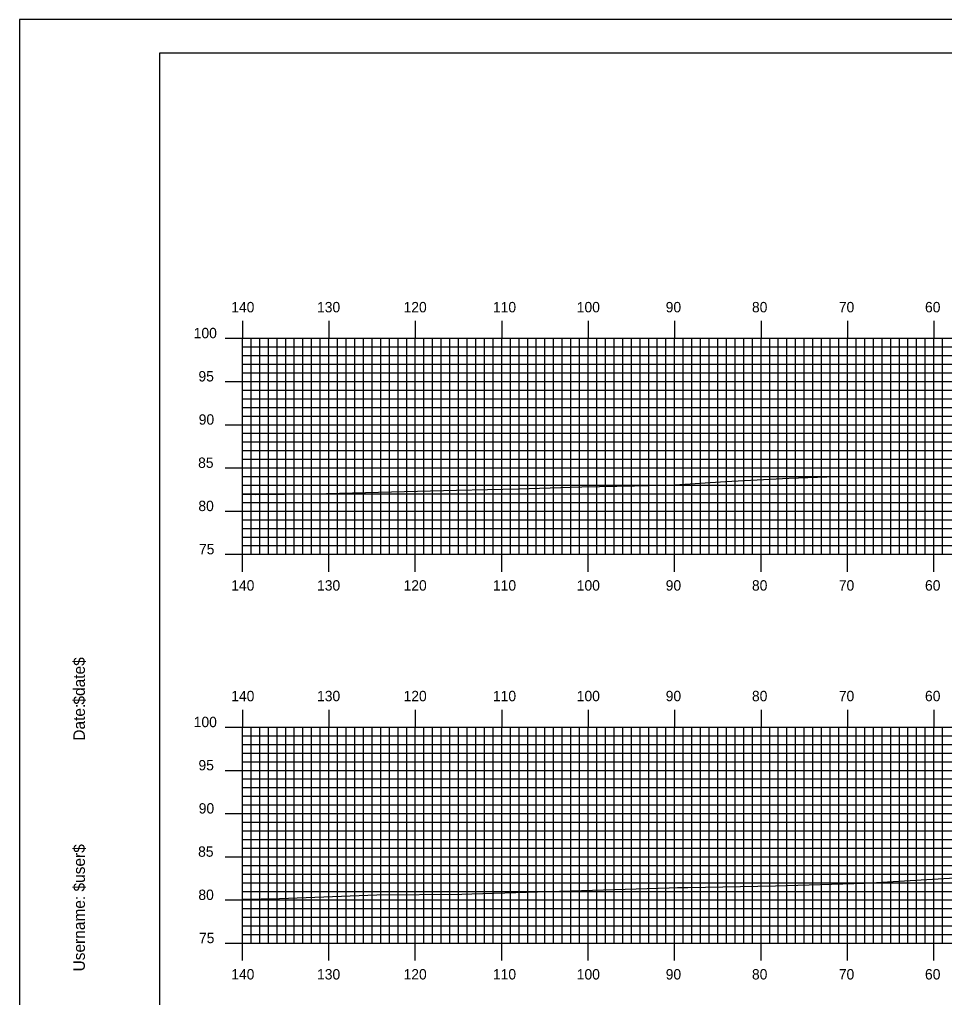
# Model space of a CAD drawing. Extents: x 1777531 to 1777875, y 442591 to 442811.
# Drawn here: x 1777531.5 to 1777638.5, y 442697.4 to 442810.5 of the extents above; entities that cross this region are included whole.
import ezdxf

# ---------------------------------------------------------------- set-up
doc = ezdxf.new("R2010")
doc.units = 0
for name, color, linetype in [('BORDER', 7, 'Continuous'), ('H_V ANNOTATION', 7, 'Continuous'), ('MAJOR', 7, 'Continuous'), ('MINOR', 7, 'Continuous'), ('PLOT BOUNDARY', 7, 'Continuous'), ('S_Roadway_Centerline', 7, 'Continuous')]:
    doc.layers.add(name, color=color, linetype=linetype)

msp = doc.modelspace()

# ---------------------------------------------------------------- linework, layer by layer
at = {"layer": 'BORDER'}
msp.add_lwpolyline([(1777547.68, 442596.67), (1777867.68, 442596.67), (1777867.68, 442806.67), (1777547.68, 442806.67)], close=True, dxfattribs=at)
at = {"layer": 'MAJOR'}
for p, q in [((1777557.28, 442775.67), (1777557.28, 442773.67)), ((1777567.28, 442775.67), (1777567.28, 442773.67)), ((1777577.28, 442775.67), (1777577.28, 442773.67)), ((1777587.28, 442775.67), (1777587.28, 442773.67)), ((1777597.28, 442775.67), (1777597.28, 442773.67)), ((1777607.28, 442775.67), (1777607.28, 442773.67)), ((1777617.28, 442775.67), (1777617.28, 442773.67)), ((1777627.28, 442775.67), (1777627.28, 442773.67)), ((1777637.28, 442775.67), (1777637.28, 442773.67)), ((1777555.27, 442773.67), (1777557.28, 442773.67)), ((1777557.28, 442773.67), (1777837.28, 442773.67)), ((1777557.28, 442748.67), (1777557.28, 442773.67)), ((1777557.28, 442748.67), (1777557.28, 442773.67)), ((1777557.28, 442773.67), (1777837.28, 442773.67)), ((1777567.28, 442748.67), (1777567.28, 442773.67)), ((1777577.28, 442748.67), (1777577.28, 442773.67)), ((1777587.28, 442748.67), (1777587.28, 442773.67)), ((1777597.28, 442748.67), (1777597.28, 442773.67)), ((1777607.28, 442748.67), (1777607.28, 442773.67)), ((1777617.28, 442748.67), (1777617.28, 442773.67)), ((1777627.28, 442748.67), (1777627.28, 442773.67)), ((1777637.28, 442748.67), (1777637.28, 442773.67)), ((1777555.27, 442768.67), (1777557.28, 442768.67)), ((1777557.28, 442768.67), (1777837.28, 442768.67)), ((1777555.27, 442763.67), (1777557.28, 442763.67)), ((1777557.28, 442763.67), (1777837.28, 442763.67)), ((1777555.27, 442758.67), (1777557.28, 442758.67)), ((1777557.28, 442758.67), (1777837.28, 442758.67)), ((1777555.27, 442753.67), (1777557.28, 442753.67)), ((1777557.28, 442753.67), (1777837.28, 442753.67)), ((1777555.27, 442748.67), (1777557.28, 442748.67)), ((1777557.28, 442748.67), (1777837.28, 442748.67)), ((1777557.28, 442748.67), (1777837.28, 442748.67)), ((1777557.28, 442746.66), (1777557.28, 442748.67)), ((1777567.28, 442746.66), (1777567.28, 442748.67)), ((1777577.28, 442746.66), (1777577.28, 442748.67)), ((1777587.28, 442746.66), (1777587.28, 442748.67)), ((1777597.28, 442746.66), (1777597.28, 442748.67)), ((1777607.28, 442746.66), (1777607.28, 442748.67)), ((1777617.28, 442746.66), (1777617.28, 442748.67)), ((1777627.28, 442746.66), (1777627.28, 442748.67)), ((1777637.28, 442746.66), (1777637.28, 442748.67)), ((1777557.28, 442730.67), (1777557.28, 442728.67)), ((1777567.28, 442730.67), (1777567.28, 442728.67)), ((1777577.28, 442730.67), (1777577.28, 442728.67)), ((1777587.28, 442730.67), (1777587.28, 442728.67)), ((1777597.28, 442730.67), (1777597.28, 442728.67)), ((1777607.28, 442730.67), (1777607.28, 442728.67)), ((1777617.28, 442730.67), (1777617.28, 442728.67)), ((1777627.28, 442730.67), (1777627.28, 442728.67)), ((1777637.28, 442730.67), (1777637.28, 442728.67)), ((1777555.27, 442728.67), (1777557.28, 442728.67)), ((1777557.28, 442728.67), (1777837.28, 442728.67)), ((1777557.28, 442703.67), (1777557.28, 442728.67)), ((1777557.28, 442703.67), (1777557.28, 442728.67)), ((1777557.28, 442728.67), (1777837.28, 442728.67)), ((1777567.28, 442703.67), (1777567.28, 442728.67)), ((1777577.28, 442703.67), (1777577.28, 442728.67)), ((1777587.28, 442703.67), (1777587.28, 442728.67)), ((1777597.28, 442703.67), (1777597.28, 442728.67)), ((1777607.28, 442703.67), (1777607.28, 442728.67)), ((1777617.28, 442703.67), (1777617.28, 442728.67)), ((1777627.28, 442703.67), (1777627.28, 442728.67)), ((1777637.28, 442703.67), (1777637.28, 442728.67)), ((1777555.27, 442723.67), (1777557.28, 442723.67)), ((1777557.28, 442723.67), (1777837.28, 442723.67)), ((1777555.27, 442718.67), (1777557.28, 442718.67)), ((1777557.28, 442718.67), (1777837.28, 442718.67)), ((1777555.27, 442713.67), (1777557.28, 442713.67)), ((1777557.28, 442713.67), (1777837.28, 442713.67)), ((1777555.27, 442708.67), (1777557.28, 442708.67)), ((1777557.28, 442708.67), (1777837.28, 442708.67)), ((1777555.27, 442703.67), (1777557.28, 442703.67)), ((1777557.28, 442703.67), (1777837.28, 442703.67)), ((1777557.28, 442703.67), (1777837.28, 442703.67)), ((1777557.28, 442701.66), (1777557.28, 442703.67)), ((1777567.28, 442701.66), (1777567.28, 442703.67)), ((1777577.28, 442701.66), (1777577.28, 442703.67)), ((1777587.28, 442701.66), (1777587.28, 442703.67)), ((1777597.28, 442701.66), (1777597.28, 442703.67)), ((1777607.28, 442701.66), (1777607.28, 442703.67)), ((1777617.28, 442701.66), (1777617.28, 442703.67)), ((1777627.28, 442701.66), (1777627.28, 442703.67)), ((1777637.28, 442701.66), (1777637.28, 442703.67))]:
    msp.add_line(p, q, dxfattribs=at)
at = {"layer": 'MINOR'}
for p, q in [((1777557.28, 442772.67), (1777837.28, 442772.67)), ((1777557.28, 442772.67), (1777559.28, 442772.67)), ((1777558.28, 442748.67), (1777558.28, 442773.67)), ((1777559.28, 442748.67), (1777559.28, 442773.67)), ((1777560.28, 442748.67), (1777560.28, 442773.67)), ((1777561.28, 442748.67), (1777561.28, 442773.67)), ((1777562.28, 442748.67), (1777562.28, 442773.67)), ((1777563.28, 442748.67), (1777563.28, 442773.67)), ((1777564.28, 442748.67), (1777564.28, 442773.67)), ((1777565.28, 442748.67), (1777565.28, 442773.67)), ((1777566.28, 442748.67), (1777566.28, 442773.67)), ((1777568.28, 442748.67), (1777568.28, 442773.67)), ((1777569.28, 442748.67), (1777569.28, 442773.67)), ((1777570.28, 442748.67), (1777570.28, 442773.67)), ((1777571.28, 442748.67), (1777571.28, 442773.67)), ((1777572.28, 442748.67), (1777572.28, 442773.67)), ((1777573.28, 442748.67), (1777573.28, 442773.67)), ((1777574.28, 442748.67), (1777574.28, 442773.67)), ((1777575.28, 442748.67), (1777575.28, 442773.67)), ((1777576.28, 442748.67), (1777576.28, 442773.67)), ((1777578.28, 442748.67), (1777578.28, 442773.67)), ((1777579.28, 442748.67), (1777579.28, 442773.67)), ((1777580.28, 442748.67), (1777580.28, 442773.67)), ((1777581.28, 442748.67), (1777581.28, 442773.67)), ((1777582.28, 442748.67), (1777582.28, 442773.67)), ((1777583.28, 442748.67), (1777583.28, 442773.67)), ((1777584.28, 442748.67), (1777584.28, 442773.67)), ((1777585.28, 442748.67), (1777585.28, 442773.67)), ((1777586.28, 442748.67), (1777586.28, 442773.67)), ((1777588.28, 442748.67), (1777588.28, 442773.67)), ((1777589.28, 442748.67), (1777589.28, 442773.67)), ((1777590.28, 442748.67), (1777590.28, 442773.67)), ((1777591.28, 442748.67), (1777591.28, 442773.67)), ((1777592.28, 442748.67), (1777592.28, 442773.67)), ((1777593.28, 442748.67), (1777593.28, 442773.67)), ((1777594.28, 442748.67), (1777594.28, 442773.67)), ((1777595.28, 442748.67), (1777595.28, 442773.67)), ((1777596.28, 442748.67), (1777596.28, 442773.67)), ((1777598.28, 442748.67), (1777598.28, 442773.67)), ((1777599.28, 442748.67), (1777599.28, 442773.67)), ((1777600.28, 442748.67), (1777600.28, 442773.67)), ((1777601.28, 442748.67), (1777601.28, 442773.67)), ((1777602.28, 442748.67), (1777602.28, 442773.67)), ((1777603.28, 442748.67), (1777603.28, 442773.67)), ((1777604.28, 442748.67), (1777604.28, 442773.67)), ((1777605.28, 442748.67), (1777605.28, 442773.67)), ((1777606.28, 442748.67), (1777606.28, 442773.67)), ((1777608.28, 442748.67), (1777608.28, 442773.67)), ((1777609.28, 442748.67), (1777609.28, 442773.67)), ((1777610.28, 442748.67), (1777610.28, 442773.67)), ((1777611.28, 442748.67), (1777611.28, 442773.67)), ((1777612.28, 442748.67), (1777612.28, 442773.67)), ((1777613.28, 442748.67), (1777613.28, 442773.67)), ((1777614.28, 442748.67), (1777614.28, 442773.67)), ((1777615.28, 442748.67), (1777615.28, 442773.67)), ((1777616.28, 442748.67), (1777616.28, 442773.67)), ((1777618.28, 442748.67), (1777618.28, 442773.67)), ((1777619.28, 442748.67), (1777619.28, 442773.67)), ((1777620.28, 442748.67), (1777620.28, 442773.67)), ((1777621.28, 442748.67), (1777621.28, 442773.67)), ((1777622.28, 442748.67), (1777622.28, 442773.67)), ((1777623.28, 442748.67), (1777623.28, 442773.67)), ((1777624.28, 442748.67), (1777624.28, 442773.67)), ((1777625.28, 442748.67), (1777625.28, 442773.67)), ((1777626.28, 442748.67), (1777626.28, 442773.67)), ((1777628.28, 442748.67), (1777628.28, 442773.67)), ((1777629.28, 442748.67), (1777629.28, 442773.67)), ((1777630.28, 442748.67), (1777630.28, 442773.67)), ((1777631.28, 442748.67), (1777631.28, 442773.67)), ((1777632.28, 442748.67), (1777632.28, 442773.67)), ((1777633.28, 442748.67), (1777633.28, 442773.67)), ((1777634.28, 442748.67), (1777634.28, 442773.67)), ((1777635.28, 442748.67), (1777635.28, 442773.67)), ((1777636.28, 442748.67), (1777636.28, 442773.67)), ((1777638.28, 442748.67), (1777638.28, 442773.67)), ((1777557.28, 442771.67), (1777837.28, 442771.67)), ((1777557.28, 442771.67), (1777559.28, 442771.67)), ((1777557.28, 442770.67), (1777837.28, 442770.67)), ((1777557.28, 442770.67), (1777559.28, 442770.67)), ((1777557.28, 442769.67), (1777837.28, 442769.67)), ((1777557.28, 442769.67), (1777559.28, 442769.67)), ((1777557.28, 442767.67), (1777837.28, 442767.67)), ((1777557.28, 442767.67), (1777559.28, 442767.67)), ((1777557.28, 442766.67), (1777837.28, 442766.67)), ((1777557.28, 442766.67), (1777559.28, 442766.67)), ((1777557.28, 442765.67), (1777837.28, 442765.67)), ((1777557.28, 442765.67), (1777559.28, 442765.67)), ((1777557.28, 442764.67), (1777837.28, 442764.67)), ((1777557.28, 442764.67), (1777559.28, 442764.67)), ((1777557.28, 442762.67), (1777837.28, 442762.67)), ((1777557.28, 442762.67), (1777559.28, 442762.67)), ((1777557.28, 442761.67), (1777837.28, 442761.67)), ((1777557.28, 442761.67), (1777559.28, 442761.67)), ((1777557.28, 442760.67), (1777837.28, 442760.67)), ((1777557.28, 442760.67), (1777559.28, 442760.67)), ((1777557.28, 442759.67), (1777837.28, 442759.67)), ((1777557.28, 442759.67), (1777559.28, 442759.67)), ((1777557.28, 442757.67), (1777837.28, 442757.67)), ((1777557.28, 442757.67), (1777559.28, 442757.67)), ((1777557.28, 442756.67), (1777837.28, 442756.67)), ((1777557.28, 442756.67), (1777559.28, 442756.67)), ((1777557.28, 442755.67), (1777837.28, 442755.67)), ((1777557.28, 442755.67), (1777559.28, 442755.67)), ((1777557.28, 442754.67), (1777837.28, 442754.67)), ((1777557.28, 442754.67), (1777559.28, 442754.67)), ((1777557.28, 442752.67), (1777837.28, 442752.67)), ((1777557.28, 442752.67), (1777559.28, 442752.67)), ((1777557.28, 442751.67), (1777837.28, 442751.67)), ((1777557.28, 442751.67), (1777559.28, 442751.67)), ((1777557.28, 442750.67), (1777837.28, 442750.67)), ((1777557.28, 442750.67), (1777559.28, 442750.67)), ((1777557.28, 442749.67), (1777837.28, 442749.67)), ((1777557.28, 442749.67), (1777559.28, 442749.67)), ((1777558.28, 442703.67), (1777558.28, 442728.67)), ((1777559.28, 442703.67), (1777559.28, 442728.67)), ((1777560.28, 442703.67), (1777560.28, 442728.67)), ((1777561.28, 442703.67), (1777561.28, 442728.67)), ((1777562.28, 442703.67), (1777562.28, 442728.67)), ((1777563.28, 442703.67), (1777563.28, 442728.67)), ((1777564.28, 442703.67), (1777564.28, 442728.67)), ((1777565.28, 442703.67), (1777565.28, 442728.67)), ((1777566.28, 442703.67), (1777566.28, 442728.67)), ((1777568.28, 442703.67), (1777568.28, 442728.67)), ((1777569.28, 442703.67), (1777569.28, 442728.67)), ((1777570.28, 442703.67), (1777570.28, 442728.67)), ((1777571.28, 442703.67), (1777571.28, 442728.67)), ((1777572.28, 442703.67), (1777572.28, 442728.67)), ((1777573.28, 442703.67), (1777573.28, 442728.67)), ((1777574.28, 442703.67), (1777574.28, 442728.67)), ((1777575.28, 442703.67), (1777575.28, 442728.67)), ((1777576.28, 442703.67), (1777576.28, 442728.67)), ((1777578.28, 442703.67), (1777578.28, 442728.67)), ((1777579.28, 442703.67), (1777579.28, 442728.67)), ((1777580.28, 442703.67), (1777580.28, 442728.67)), ((1777581.28, 442703.67), (1777581.28, 442728.67)), ((1777582.28, 442703.67), (1777582.28, 442728.67)), ((1777583.28, 442703.67), (1777583.28, 442728.67)), ((1777584.28, 442703.67), (1777584.28, 442728.67)), ((1777585.28, 442703.67), (1777585.28, 442728.67)), ((1777586.28, 442703.67), (1777586.28, 442728.67)), ((1777588.28, 442703.67), (1777588.28, 442728.67)), ((1777589.28, 442703.67), (1777589.28, 442728.67)), ((1777590.28, 442703.67), (1777590.28, 442728.67)), ((1777591.28, 442703.67), (1777591.28, 442728.67)), ((1777592.28, 442703.67), (1777592.28, 442728.67)), ((1777593.28, 442703.67), (1777593.28, 442728.67)), ((1777594.28, 442703.67), (1777594.28, 442728.67)), ((1777595.28, 442703.67), (1777595.28, 442728.67)), ((1777596.28, 442703.67), (1777596.28, 442728.67)), ((1777598.28, 442703.67), (1777598.28, 442728.67)), ((1777599.28, 442703.67), (1777599.28, 442728.67)), ((1777600.28, 442703.67), (1777600.28, 442728.67)), ((1777601.28, 442703.67), (1777601.28, 442728.67)), ((1777602.28, 442703.67), (1777602.28, 442728.67)), ((1777603.28, 442703.67), (1777603.28, 442728.67)), ((1777604.28, 442703.67), (1777604.28, 442728.67)), ((1777605.28, 442703.67), (1777605.28, 442728.67)), ((1777606.28, 442703.67), (1777606.28, 442728.67)), ((1777608.28, 442703.67), (1777608.28, 442728.67)), ((1777609.28, 442703.67), (1777609.28, 442728.67)), ((1777610.28, 442703.67), (1777610.28, 442728.67)), ((1777611.28, 442703.67), (1777611.28, 442728.67)), ((1777612.28, 442703.67), (1777612.28, 442728.67)), ((1777613.28, 442703.67), (1777613.28, 442728.67)), ((1777614.28, 442703.67), (1777614.28, 442728.67)), ((1777615.28, 442703.67), (1777615.28, 442728.67)), ((1777616.28, 442703.67), (1777616.28, 442728.67)), ((1777618.28, 442703.67), (1777618.28, 442728.67)), ((1777619.28, 442703.67), (1777619.28, 442728.67)), ((1777620.28, 442703.67), (1777620.28, 442728.67)), ((1777621.28, 442703.67), (1777621.28, 442728.67)), ((1777622.28, 442703.67), (1777622.28, 442728.67)), ((1777623.28, 442703.67), (1777623.28, 442728.67)), ((1777624.28, 442703.67), (1777624.28, 442728.67)), ((1777625.28, 442703.67), (1777625.28, 442728.67)), ((1777626.28, 442703.67), (1777626.28, 442728.67)), ((1777628.28, 442703.67), (1777628.28, 442728.67)), ((1777629.28, 442703.67), (1777629.28, 442728.67)), ((1777630.28, 442703.67), (1777630.28, 442728.67)), ((1777631.28, 442703.67), (1777631.28, 442728.67)), ((1777632.28, 442703.67), (1777632.28, 442728.67)), ((1777633.28, 442703.67), (1777633.28, 442728.67)), ((1777634.28, 442703.67), (1777634.28, 442728.67)), ((1777635.28, 442703.67), (1777635.28, 442728.67)), ((1777636.28, 442703.67), (1777636.28, 442728.67)), ((1777638.28, 442703.67), (1777638.28, 442728.67)), ((1777557.28, 442727.67), (1777837.28, 442727.67)), ((1777557.28, 442727.67), (1777559.28, 442727.67)), ((1777557.28, 442726.67), (1777837.28, 442726.67)), ((1777557.28, 442726.67), (1777559.28, 442726.67)), ((1777557.28, 442725.67), (1777837.28, 442725.67)), ((1777557.28, 442725.67), (1777559.28, 442725.67)), ((1777557.28, 442724.67), (1777837.28, 442724.67)), ((1777557.28, 442724.67), (1777559.28, 442724.67)), ((1777557.28, 442722.67), (1777837.28, 442722.67)), ((1777557.28, 442722.67), (1777559.28, 442722.67)), ((1777557.28, 442721.67), (1777837.28, 442721.67)), ((1777557.28, 442721.67), (1777559.28, 442721.67)), ((1777557.28, 442720.67), (1777837.28, 442720.67)), ((1777557.28, 442720.67), (1777559.28, 442720.67)), ((1777557.28, 442719.67), (1777837.28, 442719.67)), ((1777557.28, 442719.67), (1777559.28, 442719.67)), ((1777557.28, 442717.67), (1777837.28, 442717.67)), ((1777557.28, 442717.67), (1777559.28, 442717.67)), ((1777557.28, 442716.67), (1777837.28, 442716.67)), ((1777557.28, 442716.67), (1777559.28, 442716.67)), ((1777557.28, 442715.67), (1777837.28, 442715.67)), ((1777557.28, 442715.67), (1777559.28, 442715.67)), ((1777557.28, 442714.67), (1777837.28, 442714.67)), ((1777557.28, 442714.67), (1777559.28, 442714.67)), ((1777557.28, 442712.67), (1777837.28, 442712.67)), ((1777557.28, 442712.67), (1777559.28, 442712.67)), ((1777557.28, 442711.67), (1777837.28, 442711.67)), ((1777557.28, 442711.67), (1777559.28, 442711.67)), ((1777557.28, 442710.67), (1777837.28, 442710.67)), ((1777557.28, 442710.67), (1777559.28, 442710.67)), ((1777557.28, 442709.67), (1777837.28, 442709.67)), ((1777557.28, 442709.67), (1777559.28, 442709.67)), ((1777557.28, 442707.67), (1777837.28, 442707.67)), ((1777557.28, 442707.67), (1777559.28, 442707.67)), ((1777557.28, 442706.67), (1777837.28, 442706.67)), ((1777557.28, 442706.67), (1777559.28, 442706.67)), ((1777557.28, 442705.67), (1777837.28, 442705.67)), ((1777557.28, 442705.67), (1777559.28, 442705.67)), ((1777557.28, 442704.67), (1777837.28, 442704.67)), ((1777557.28, 442704.67), (1777559.28, 442704.67))]:
    msp.add_line(p, q, dxfattribs=at)
at = {"layer": 'PLOT BOUNDARY'}
msp.add_lwpolyline([(1777531.49, 442590.55), (1777871.49, 442590.55), (1777871.49, 442810.55), (1777531.49, 442810.55)], close=True, dxfattribs=at)
at = {"layer": 'S_Roadway_Centerline'}
for points in [[(1777557.28, 442755.63), (1777558.78, 442755.6), (1777565.49, 442755.65), (1777582.04, 442756.1), (1777589.23, 442756.26), (1777596.54, 442756.49), (1777602.62, 442756.6), (1777607.29, 442756.7), (1777613.15, 442757.09), (1777620.49, 442757.48), (1777626.02, 442757.69), (1777642.13, 442757.73)], [(1777557.28, 442708.75), (1777561.56, 442708.86), (1777572.82, 442709.28), (1777582.66, 442709.35), (1777583.81, 442709.38), (1777606.64, 442710.08), (1777607.62, 442710.11), (1777608.79, 442710.11), (1777618.96, 442710.29), (1777629.31, 442710.62), (1777641.65, 442711.33)]]:
    msp.add_lwpolyline(points, dxfattribs=at)

# ---------------------------------------------------------------- texts
at = {"layer": 'BORDER'}
for s, p in [('$date$', (1777539.05, 442731.28)), ('Date:', (1777539.05, 442727.1)), ('$user$', (1777539.05, 442709.65)), ('Username:', (1777539.05, 442700.4))]:
    msp.add_text(s, height=1.339, rotation=90, dxfattribs=at).set_placement(p)
at = {"layer": 'H_V ANNOTATION'}
for s, p in [('140', (1777555.98, 442776.67)), ('130', (1777565.91, 442776.67)), ('120', (1777575.92, 442776.67)), ('110', (1777586.26, 442776.67)), ('100', (1777595.96, 442776.67)), ('90', (1777606.25, 442776.67)), ('80', (1777616.23, 442776.67)), ('70', (1777626.28, 442776.67)), ('60', (1777636.25, 442776.67)), ('100', (1777551.64, 442773.67)), ('95', (1777552.19, 442768.67)), ('90', (1777552.22, 442763.67)), ('85', (1777552.15, 442758.67)), ('80', (1777552.18, 442753.67)), ('75', (1777552.25, 442748.67)), ('140', (1777555.98, 442744.47)), ('130', (1777565.91, 442744.47)), ('120', (1777575.92, 442744.47)), ('110', (1777586.26, 442744.47)), ('100', (1777595.96, 442744.47)), ('90', (1777606.25, 442744.47)), ('80', (1777616.23, 442744.47)), ('70', (1777626.28, 442744.47)), ('60', (1777636.25, 442744.47)), ('140', (1777555.98, 442731.67)), ('130', (1777565.91, 442731.67)), ('120', (1777575.92, 442731.67)), ('110', (1777586.26, 442731.67)), ('100', (1777595.96, 442731.67)), ('90', (1777606.25, 442731.67)), ('80', (1777616.23, 442731.67)), ('70', (1777626.28, 442731.67)), ('60', (1777636.25, 442731.67)), ('100', (1777551.64, 442728.67)), ('95', (1777552.19, 442723.67)), ('90', (1777552.22, 442718.67)), ('85', (1777552.15, 442713.67)), ('80', (1777552.18, 442708.67)), ('75', (1777552.25, 442703.67)), ('140', (1777555.98, 442699.47)), ('130', (1777565.91, 442699.47)), ('120', (1777575.92, 442699.47)), ('110', (1777586.26, 442699.47)), ('100', (1777595.96, 442699.47)), ('90', (1777606.25, 442699.47)), ('80', (1777616.23, 442699.47)), ('70', (1777626.28, 442699.47)), ('60', (1777636.25, 442699.47))]:
    msp.add_text(s, height=1.2, dxfattribs=at).set_placement(p)
at = {"layer": 'MAJOR'}
for p in [(1777557.27, 442748.67), (1777557.27, 442703.67)]:
    msp.add_text('-', height=0.012, dxfattribs=at).set_placement(p)

doc.saveas('drawing.dxf')
